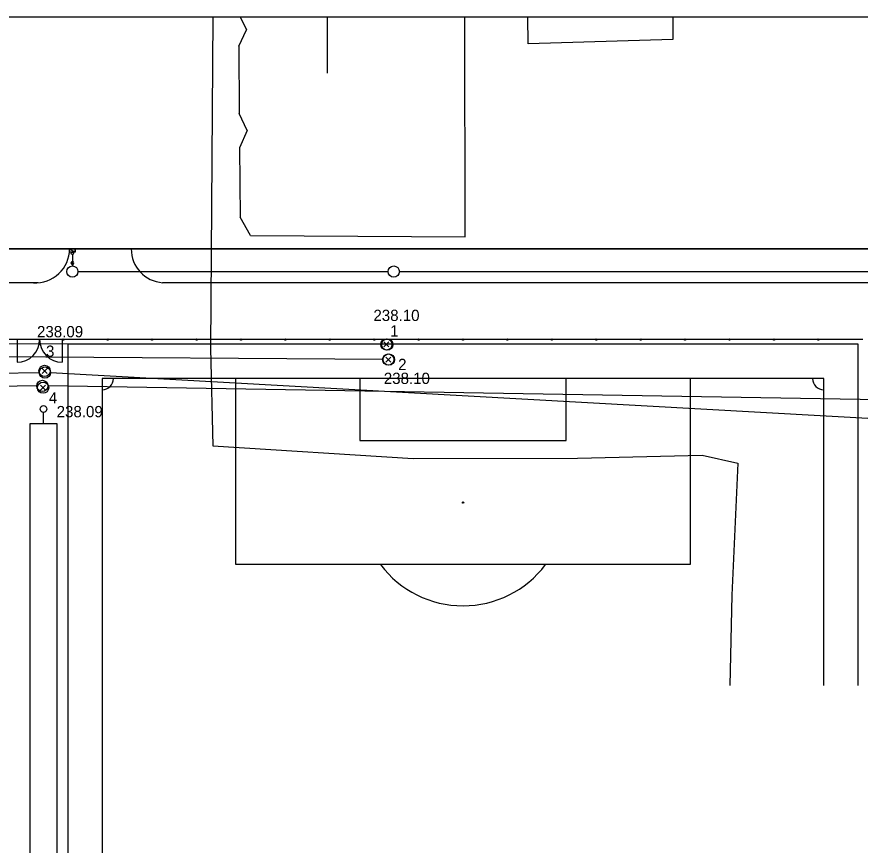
# Model space of a CAD drawing. Extents: x -264125 to -263915, y -1242307 to -1242159.
# Drawn here: x -264047.1 to -263972.3, y -1242232.4 to -1242158.9 of the extents above; entities that cross this region are included whole.
import ezdxf

# ---------------------------------------------------------------- set-up
doc = ezdxf.new("R2010")
doc.units = 0
for name, color, linetype in [('KFA_BODY_CISLO', 7, 'Continuous'), ('KFA_BODY_SYMBOL', 7, 'Continuous'), ('KFA_BODY_VYSKA', 7, 'Continuous'), ('KFA_JESTV_IS_DSP', 7, 'Continuous'), ('KFA_SITUACIA_DSP', 7, 'Continuous'), ('KFA_SO_40-3_SACHTY_POKLOPY', 7, 'Continuous'), ('RAM_NA_TLAC_A3_1-500', 7, 'Continuous')]:
    doc.layers.add(name, color=color, linetype=linetype)

msp = doc.modelspace()

# ---------------------------------------------------------------- linework, layer by layer
at = {"layer": 'KFA_BODY_SYMBOL'}
for p, q in [((-264014.53, -1242188.177), (-264014.088, -1242187.735)), ((-264014.088, -1242188.177), (-264014.53, -1242187.735)), ((-264014.367, -1242189.52), (-264013.925, -1242189.078)), ((-264013.925, -1242189.52), (-264014.367, -1242189.078)), ((-264044.852, -1242190.523), (-264044.41, -1242190.081)), ((-264044.41, -1242190.523), (-264044.852, -1242190.081)), ((-264044.979, -1242192.013), (-264044.537, -1242191.571)), ((-264044.537, -1242192.013), (-264044.979, -1242191.571))]:
    msp.add_line(p, q, dxfattribs=at)
at = {"layer": 'KFA_JESTV_IS_DSP'}
for p, q in [((-264029.717, -1242158.913), (-264029.913, -1242188.318)), ((-264014.738, -1242187.967), (-264101.789, -1242187.812)), ((-264029.913, -1242188.318), (-264029.719, -1242196.934)), ((-264014.599, -1242189.295), (-264103.868, -1242188.645)), ((-264045.101, -1242190.466), (-264103.724, -1242191.719)), ((-263970.367, -1242194.605), (-264044.102, -1242190.483)), ((-264045.328, -1242191.64), (-264101.25, -1242192.452)), ((-263970.542, -1242192.875), (-264044.328, -1242191.641)), ((-264029.719, -1242196.934), (-264011.931, -1242198.062)), ((-264011.931, -1242198.062), (-263997.36, -1242198.031)), ((-263997.36, -1242198.031), (-263986.295, -1242197.77)), ((-263986.295, -1242197.77), (-263983.14, -1242198.474)), ((-263983.14, -1242198.474), (-263983.691, -1242210.183)), ((-263983.691, -1242210.183), (-263983.847, -1242218.208))]:
    msp.add_line(p, q, dxfattribs=at)
for centre in [(-264014.238, -1242187.968), (-264014.099, -1242189.299), (-264044.601, -1242190.456), (-264044.828, -1242191.633)]:
    msp.add_circle(centre, 0.5, dxfattribs=at)
at = {"layer": 'KFA_SITUACIA_DSP'}
for p, q in [((-264027.291, -1242158.913), (-264026.72, -1242160.07)), ((-264007.34, -1242178.42), (-264007.368, -1242158.913)), ((-264001.73, -1242161.29), (-264001.756, -1242158.913)), ((-263988.908, -1242158.913), (-263988.91, -1242160.93)), ((-264027.41, -1242161.52), (-264026.72, -1242160.07)), ((-264027.41, -1242161.52), (-264027.36, -1242167.48)), ((-263988.91, -1242160.93), (-264001.73, -1242161.29)), ((-264026.65, -1242168.99), (-264027.36, -1242167.48)), ((-264026.65, -1242168.99), (-264027.34, -1242170.52)), ((-264027.34, -1242170.52), (-264027.29, -1242176.68)), ((-264026.37, -1242178.31), (-264027.29, -1242176.68)), ((-264026.37, -1242178.31), (-264007.34, -1242178.42)), ((-264124.579, -1242179.482), (-263959.468, -1242179.482)), ((-263959.468, -1242179.482), (-264124.579, -1242179.482)), ((-263959.468, -1242179.482), (-264077.23, -1242179.482)), ((-264042.417, -1242179.482), (-264041.917, -1242179.482)), ((-264042.417, -1242179.772), (-264042.417, -1242179.482)), ((-264042.417, -1242179.482), (-264041.917, -1242179.772)), ((-264042.417, -1242179.482), (-264041.917, -1242179.772)), ((-264041.917, -1242179.482), (-264042.417, -1242179.482)), ((-264041.917, -1242179.482), (-264041.917, -1242179.772)), ((-264041.917, -1242179.772), (-264041.917, -1242179.482)), ((-264041.917, -1242179.772), (-264042.417, -1242179.772)), ((-264042.167, -1242179.972), (-264042.167, -1242181)), ((-264041.667, -1242181.5), (-264014.161, -1242181.5)), ((-264013.161, -1242181.5), (-263964.161, -1242181.5)), ((-264045.204, -1242182.482), (-264124.579, -1242182.482)), ((-263960.118, -1242182.482), (-264034.158, -1242182.482)), ((-263972.068, -1242187.532), (-264118.068, -1242187.532)), ((-264047.068, -1242187.532), (-264047.068, -1242189.532)), ((-264044.568, -1242187.532), (-264045.568, -1242187.532)), ((-264043.068, -1242187.532), (-264043.068, -1242189.532)), ((-264042.908, -1242187.532), (-264043.028, -1242187.532)), ((-264042.968, -1242187.592), (-264042.968, -1242187.472)), ((-264039.089, -1242187.532), (-264038.969, -1242187.532)), ((-264039.029, -1242187.592), (-264039.029, -1242187.472)), ((-264035.15, -1242187.532), (-264035.03, -1242187.532)), ((-264035.09, -1242187.592), (-264035.09, -1242187.472)), ((-264031.211, -1242187.532), (-264031.091, -1242187.532)), ((-264031.151, -1242187.592), (-264031.151, -1242187.472)), ((-264027.272, -1242187.532), (-264027.152, -1242187.532)), ((-264027.212, -1242187.592), (-264027.212, -1242187.472)), ((-264023.333, -1242187.532), (-264023.213, -1242187.532)), ((-264023.273, -1242187.592), (-264023.273, -1242187.472)), ((-264019.394, -1242187.532), (-264019.274, -1242187.532)), ((-264019.334, -1242187.592), (-264019.334, -1242187.472)), ((-264015.456, -1242187.532), (-264015.336, -1242187.532)), ((-264015.396, -1242187.592), (-264015.396, -1242187.472)), ((-264011.517, -1242187.532), (-264011.397, -1242187.532)), ((-264011.457, -1242187.592), (-264011.457, -1242187.472)), ((-264007.578, -1242187.532), (-264007.458, -1242187.532)), ((-264007.518, -1242187.592), (-264007.518, -1242187.472)), ((-264003.639, -1242187.532), (-264003.519, -1242187.532)), ((-264003.579, -1242187.592), (-264003.579, -1242187.472)), ((-263999.7, -1242187.532), (-263999.58, -1242187.532)), ((-263999.64, -1242187.592), (-263999.64, -1242187.472)), ((-263995.761, -1242187.532), (-263995.641, -1242187.532)), ((-263995.701, -1242187.592), (-263995.701, -1242187.472)), ((-263991.822, -1242187.532), (-263991.702, -1242187.532)), ((-263991.762, -1242187.592), (-263991.762, -1242187.472)), ((-263987.883, -1242187.532), (-263987.763, -1242187.532)), ((-263987.823, -1242187.592), (-263987.823, -1242187.472)), ((-263983.944, -1242187.532), (-263983.824, -1242187.532)), ((-263983.884, -1242187.592), (-263983.884, -1242187.472)), ((-263980.006, -1242187.532), (-263979.886, -1242187.532)), ((-263979.946, -1242187.592), (-263979.946, -1242187.472)), ((-263976.067, -1242187.532), (-263975.947, -1242187.532)), ((-263976.007, -1242187.592), (-263976.007, -1242187.472)), ((-263972.468, -1242187.932), (-264042.568, -1242187.932)), ((-264042.568, -1242187.932), (-264042.568, -1242294.032)), ((-263972.468, -1242218.208), (-263972.468, -1242187.932)), ((-263975.518, -1242190.982), (-264039.518, -1242190.982)), ((-264039.518, -1242190.982), (-264039.518, -1242290.982)), ((-264027.678, -1242207.482), (-264027.678, -1242190.982)), ((-264016.678, -1242190.982), (-264016.678, -1242196.482)), ((-263998.358, -1242196.482), (-263998.358, -1242190.982)), ((-263987.358, -1242190.982), (-263987.358, -1242207.482)), ((-263975.518, -1242218.208), (-263975.518, -1242190.982)), ((-264044.727, -1242194.982), (-264044.727, -1242193.982)), ((-264043.527, -1242194.982), (-264045.927, -1242194.982)), ((-264045.927, -1242194.982), (-264045.927, -1242293.982)), ((-264043.527, -1242293.982), (-264043.527, -1242194.982)), ((-264016.678, -1242196.482), (-263998.358, -1242196.482)), ((-263987.358, -1242207.482), (-264027.678, -1242207.482))]:
    msp.add_line(p, q, dxfattribs=at)
for centre, radius in [((-264042.167, -1242179.872), 0.1), ((-264042.167, -1242181.5), 0.5), ((-264013.661, -1242181.5), 0.5), ((-264042.968, -1242187.532), 0.06), ((-264039.029, -1242187.532), 0.06), ((-264035.09, -1242187.532), 0.06), ((-264031.151, -1242187.532), 0.06), ((-264027.212, -1242187.532), 0.06), ((-264023.273, -1242187.532), 0.06), ((-264019.334, -1242187.532), 0.06), ((-264015.396, -1242187.532), 0.06), ((-264011.457, -1242187.532), 0.06), ((-264007.518, -1242187.532), 0.06), ((-264003.579, -1242187.532), 0.06), ((-263999.64, -1242187.532), 0.06), ((-263995.701, -1242187.532), 0.06), ((-263991.762, -1242187.532), 0.06), ((-263987.823, -1242187.532), 0.06), ((-263983.884, -1242187.532), 0.06), ((-263979.946, -1242187.532), 0.06), ((-263976.007, -1242187.532), 0.06), ((-264044.727, -1242193.682), 0.3), ((-264007.518, -1242201.982), 0.06)]:
    msp.add_circle(centre, radius, dxfattribs=at)
for centre, radius, start, end in [((-264045.412, -1242179.495), 2.994, 266.03136, 0.25001), ((-264033.951, -1242179.495), 2.994, 179.74999, 266.03136), ((-264042.167, -1242180.736), 0.125, 0, 180), ((-264042.167, -1242180.736), 0.125, 180, 0), ((-264047.068, -1242187.532), 2, 270, 360), ((-264043.068, -1242187.532), 2, 180, 270), ((-264039.518, -1242190.982), 1, 270, 360), ((-263975.518, -1242190.982), 1, 180, 270), ((-264007.518, -1242201.982), 0.0303, 90, 270), ((-264007.518, -1242201.982), 0.0303, 270, 90), ((-264007.518, -1242201.982), 9.15, 216.94821, 323.05179)]:
    msp.add_arc(centre, radius, start, end, dxfattribs=at)
at = {"layer": 'KFA_SO_40-3_SACHTY_POKLOPY'}
for centre in [(-264014.309, -1242187.956), (-264014.146, -1242189.299), (-264044.631, -1242190.302), (-264044.758, -1242191.792)]:
    msp.add_circle(centre, 0.5, dxfattribs=at)
at = {"layer": 'RAM_NA_TLAC_A3_1-500'}
msp.add_line((-264019.579, -1242158.913), (-264019.579, -1242163.913), dxfattribs=at)
msp.add_lwpolyline([(-264124.579, -1242158.913), (-263914.579, -1242158.913), (-263914.579, -1242307.413), (-264124.579, -1242307.413)], close=True, dxfattribs=at)

# ---------------------------------------------------------------- texts
at = {"layer": 'KFA_BODY_CISLO'}
for s, p in [('1', (-264013.985, -1242187.266)), ('3', (-264044.507, -1242189.056)), ('2', (-264013.272, -1242190.231)), ('4', (-264044.251, -1242193.192))]:
    msp.add_text(s, height=1, dxfattribs=at).set_placement(p)
at = {"layer": 'KFA_BODY_VYSKA'}
for s, p in [('238.10', (-264015.464, -1242185.879)), ('238.09', (-264045.299, -1242187.322)), ('238.10', (-264014.544, -1242191.463)), ('238.09', (-264043.56, -1242194.413))]:
    msp.add_text(s, height=1, dxfattribs=at).set_placement(p)

doc.saveas('drawing.dxf')
